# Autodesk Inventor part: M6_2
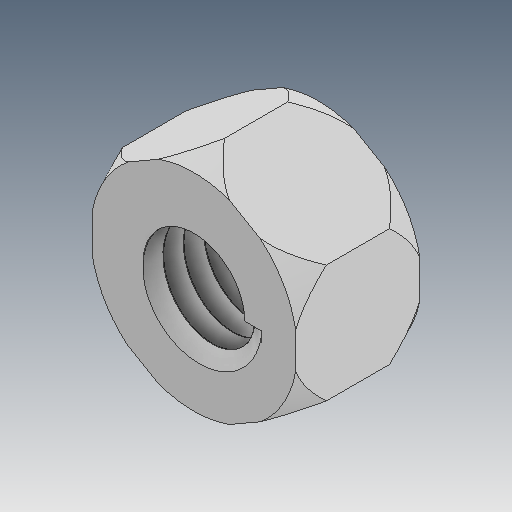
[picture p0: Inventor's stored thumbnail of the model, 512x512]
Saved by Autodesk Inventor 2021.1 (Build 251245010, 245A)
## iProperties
Created: 2019-05
Part Number: M6_2
Material: Ogólny
Document SubType Name: Modeling
Designer: user
Density: 1 g/cm^3
Appearance: Domyślna
Author: user
Revision Number: ÈÎºÎ
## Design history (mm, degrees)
feature "ÊäÈë1"
node "Bryła1"
